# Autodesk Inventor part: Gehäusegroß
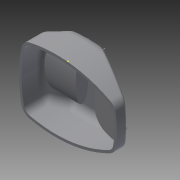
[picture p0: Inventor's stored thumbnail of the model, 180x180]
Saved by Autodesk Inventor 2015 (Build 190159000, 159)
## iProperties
Created: 2015-01
Part Number: Gehäusegroß
Material: Holz (Eiche)
Document SubType Name: Modeling
Designer: Manuel
Density: 0.76 g/cm^3
Appearance: Weißeiche - natur - mittlerer Glanz
Author: Manuel
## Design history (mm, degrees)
derived "Gehäuse_fertig.ipt"
  sketch "Skizze6"
    geometry: 1 further point
sketch "Skizze3"
  geometry: L1 (84.864, 78.184)-(77.158, 84.557); L2 (77.158, 84.557)-(78.432, 86.098); L3 (78.432, 86.098)-(86.139, 79.725); L4 (86.139, 79.725)-(84.864, 78.184); 1 further point
  constraints: 8 end point, 2 perpendicular
  dimensions: "d1" = 10 distance of L1.start L1.end; "d2" = 2 distance of L1.end L2.end; "d3" = 10 distance of L2.end L3.end
extrude "Extrusion1" join sketch "Skizze3" distance "d4" = 11; taper "d5" = 0 deg
sketch "Skizze4"
  geometry: L1 (10, 0)-(10, 11) reference; L2 (0, 11)-(10, 11); L3 (10, 11)-(10, 9); L4 (10, 9)-(0, 9); L5 (0, 9)-(0, 11); 1 further point
  constraints: 8 end point, 2 parallel, 1 horizontal, 1 perpendicular, 1 point on line
  dimensions: "d6" = 2 distance of L2.end L3.end
extrude "Extrusion2" join sketch "Skizze4" distance "d7" = 20; taper "d8" = 0 deg
fillet "Rundung1" dims "d9" = 5
sketch "Skizze5"
  geometry: 1 further point
sketch "Skizze7"
  geometry: L1 (4.039, 22.135)-(3.226, 34.893) reference; L2 (3.226, 34.893)-(-4.795, 34.382) reference; L3 (-4.795, 34.382)-(3.226, 34.893); L4 (-4.795, 34.382)-(3.226, 34.893) reference; L5 (3.226, 34.893)-(4.039, 22.135); C1 r 2.5 at (0, 0) reference; A1 r 22.5 centre (0, 0) between (-4.039, 22.135) and (4.039, 22.135) reference; A2 r 8.442 centre (-10.204, 27.901) between (-4.039, 22.135) and (-4.795, 34.382) reference; A3 r 22.5 centre (0, 0) between (4.039, 22.135) and (-4.039, 22.135); A4 r 8.442 centre (-10.204, 27.901) between (-4.039, 22.135) and (-4.795, 34.382); 1 further point
  constraints: 4 end point, 4 point on circle, 2 centre point, 1 collinear, 1 perpendicular
extrude "Extrusion3" cut sketch "Skizze7" distance "d10" = 3; taper "d11" = 0 deg
feature "Volumenkörper1::Gehäuse_fertig.ipt" dims "d0" = 100
tag "Bezeichnung1"
node "Projizierte Kontur2"
node "Volumenkörper1"
